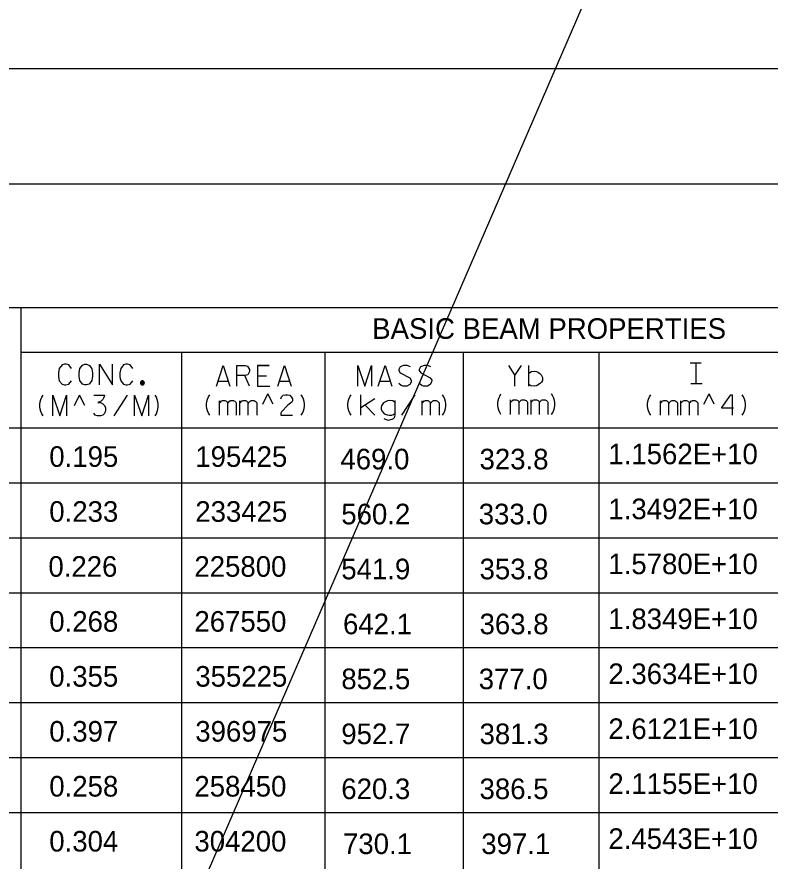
# Model space of a CAD drawing. Extents: x 635698 to 639877, y 296617 to 300175.
# Drawn here: x 636957.9 to 637067.5, y 299340.4 to 299463.3 of the extents above; entities that cross this region are included whole.
import ezdxf

# ---------------------------------------------------------------- set-up
doc = ezdxf.new("R2010")
doc.units = 0
doc.layers.add('1', color=7, linetype='Continuous')
doc.layers.add('2', color=7, linetype='Continuous')

msp = doc.modelspace()

# ---------------------------------------------------------------- linework, layer by layer
at = {"layer": '1'}
msp.add_line((637313.22, 300096.11), (636518.29, 298258.33), dxfattribs=at)
at = {"layer": '2'}
for p, q in [((636545.45, 299455.76), (637331.45, 299455.76)), ((637142.33, 299438.89), (636554.2, 299438.89)), ((637142.33, 299420.89), (636700.83, 299420.89)), ((636958.45, 299420.89), (636958.45, 299235.39)), ((637142.33, 299414.39), (636958.45, 299414.39)), ((636981.83, 299414.39), (636981.83, 299235.39)), ((637002.7, 299414.39), (637002.7, 299235.39)), ((637022.83, 299414.39), (637022.83, 299235.39)), ((637042.58, 299414.39), (637042.58, 299235.39)), ((637055.83, 299412.89), (637057.45, 299412.89)), ((637055.95, 299409.89), (637057.58, 299409.89)), ((636963.09, 299405.2), (636963.09, 299408.2)), ((636963.09, 299408.2), (636964.13, 299405.2)), ((636964.13, 299405.2), (636965.09, 299408.2)), ((636965.09, 299408.2), (636965.09, 299405.2)), ((636966.24, 299406.7), (636966.99, 299408.2)), ((636967.74, 299406.7), (636966.99, 299408.2)), ((636974.99, 299405.2), (636974.99, 299408.2)), ((636974.99, 299408.2), (636976.03, 299405.2)), ((636976.03, 299405.2), (636977, 299408.2)), ((636977, 299408.2), (636977, 299405.2)), ((636993.66, 299406.87), (636994.41, 299408.37)), ((636995.16, 299406.87), (636994.41, 299408.37)), ((637057.86, 299406.87), (637058.61, 299408.37)), ((637059.36, 299406.87), (637058.61, 299408.37)), ((637110.33, 299403.39), (636700.83, 299403.39)), ((637142.33, 299403.39), (636958.45, 299403.39)), ((637142.33, 299395.39), (636700.83, 299395.39)), ((637142.33, 299387.39), (636700.83, 299387.39)), ((637142.33, 299379.39), (636700.83, 299379.39)), ((637142.33, 299371.39), (636700.83, 299371.39)), ((637142.33, 299363.39), (636700.83, 299363.39)), ((637142.33, 299355.39), (636700.83, 299355.39)), ((637142.33, 299347.39), (636700.83, 299347.39))]:
    msp.add_line(p, q, dxfattribs=at)
for points in [[(636965.81, 299412.1), (636965.43, 299412.6), (636965.05, 299412.7), (636964.79, 299412.7), (636964.44, 299412.6), (636964.04, 299412.1), (636963.94, 299411.44), (636963.94, 299411.09), (636963.94, 299410.85), (636963.97, 299410.64), (636964.04, 299410.26), (636964.44, 299409.79), (636964.79, 299409.7), (636965.01, 299409.7), (636965.41, 299409.79), (636965.81, 299410.26)], [(636967.77, 299412.7), (636968.01, 299412.7), (636968.41, 299412.53), (636968.78, 299412.03), (636968.88, 299411.44), (636968.88, 299410.9), (636968.78, 299410.31), (636968.38, 299409.81), (636968.01, 299409.7), (636967.77, 299409.7), (636967.42, 299409.81), (636967.01, 299410.31), (636966.92, 299410.9), (636966.92, 299411.44), (636967.01, 299412.06), (636967.42, 299412.55), (636967.77, 299412.7)], [(636969.9, 299409.7), (636969.9, 299412.7), (636971.76, 299409.7), (636971.76, 299412.7)], [(636974.74, 299412.1), (636974.36, 299412.6), (636973.98, 299412.7), (636973.72, 299412.7), (636973.37, 299412.6), (636972.97, 299412.1), (636972.87, 299411.44), (636972.87, 299411.09), (636972.87, 299410.85), (636972.9, 299410.64), (636972.97, 299410.26), (636973.37, 299409.79), (636973.72, 299409.7), (636973.93, 299409.7), (636974.34, 299409.79), (636974.74, 299410.26)], [(636986.9, 299409.52), (636987.89, 299412.52), (636988.86, 299409.52)], [(636989.88, 299409.52), (636989.88, 299412.52), (636991.08, 299412.52), (636991.44, 299412.4), (636991.74, 299411.93), (636991.74, 299411.64), (636991.46, 299411.17), (636991.08, 299411.05), (636989.88, 299411.05)], [(636994.58, 299412.52), (636992.86, 299412.52), (636992.86, 299409.52), (636994.7, 299409.52)], [(636992.86, 299412.52), (636994.58, 299412.52)], [(636995.83, 299409.52), (636996.82, 299412.52), (636997.79, 299409.52)], [(637007.48, 299409.52), (637007.48, 299412.52), (637008.52, 299409.52), (637009.49, 299412.52), (637009.49, 299409.52)], [(637010.46, 299409.52), (637011.45, 299412.52), (637012.42, 299409.52)], [(637015.16, 299412.3), (637014.68, 299412.52), (637014.14, 299412.52), (637013.64, 299412.3), (637013.43, 299411.93), (637013.43, 299411.78), (637013.67, 299411.43), (637015.04, 299410.72), (637015.27, 299410.39), (637015.25, 299410.11), (637015.04, 299409.73), (637014.64, 299409.52), (637014.07, 299409.52), (637013.81, 299409.61), (637013.43, 299409.87)], [(637018.13, 299412.3), (637017.66, 299412.52), (637017.12, 299412.52), (637016.62, 299412.3), (637016.41, 299411.93), (637016.41, 299411.78), (637016.64, 299411.43), (637018.01, 299410.72), (637018.25, 299410.39), (637018.23, 299410.11), (637018.01, 299409.73), (637017.61, 299409.52), (637017.05, 299409.52), (637016.79, 299409.61), (637016.41, 299409.87)], [(637029.41, 299412.52), (637030.35, 299411.07), (637031.3, 299412.52)], [(637032.38, 299409.52), (637032.38, 299412.52)], [(637056.36, 299412.89), (637057.07, 299412.89)], [(637056.72, 299409.89), (637056.72, 299412.89)], [(636991.74, 299409.52), (636991.06, 299411.05)], [(636992.86, 299411.03), (636994.2, 299411.03)], [(636992.86, 299411.03), (636994.2, 299411.03)], [(637030.35, 299409.52), (637030.35, 299411.07)], [(637032.38, 299411.41), (637032.76, 299411.62), (637033.14, 299411.67), (637033.47, 299411.62), (637033.78, 299411.48), (637033.97, 299411.36), (637034.16, 299411.15), (637034.25, 299410.96), (637034.34, 299410.79), (637034.34, 299410.34), (637034.2, 299410.08), (637034.08, 299409.94), (637033.73, 299409.68), (637033.49, 299409.56), (637033.14, 299409.52), (637032.67, 299409.56), (637032.38, 299409.75)], [(636976.42, 299409.98), (636976.42, 299410.01), (636976.41, 299410.04), (636976.4, 299410.07), (636976.39, 299410.1), (636976.38, 299410.12), (636976.36, 299410.15), (636976.35, 299410.17), (636976.32, 299410.19), (636976.3, 299410.21), (636976.28, 299410.23), (636976.25, 299410.24), (636976.22, 299410.25), (636976.19, 299410.26), (636976.16, 299410.26), (636976.13, 299410.27), (636976.1, 299410.26), (636976.07, 299410.26), (636976.05, 299410.25), (636976.02, 299410.24), (636975.99, 299410.23), (636975.97, 299410.21), (636975.94, 299410.19), (636975.92, 299410.17), (636975.9, 299410.15), (636975.89, 299410.12), (636975.87, 299410.1), (636975.86, 299410.07), (636975.85, 299410.04), (636975.85, 299410.01), (636975.85, 299409.98), (636975.85, 299409.95), (636975.85, 299409.92), (636975.86, 299409.89), (636975.87, 299409.86), (636975.89, 299409.84), (636975.9, 299409.81), (636975.92, 299409.79), (636975.94, 299409.77), (636975.97, 299409.75), (636975.99, 299409.73), (636976.02, 299409.72), (636976.05, 299409.71), (636976.07, 299409.7), (636976.1, 299409.7), (636976.13, 299409.7), (636976.16, 299409.7), (636976.19, 299409.7), (636976.22, 299409.71), (636976.25, 299409.72), (636976.28, 299409.73), (636976.3, 299409.75), (636976.32, 299409.77), (636976.35, 299409.79), (636976.36, 299409.81), (636976.38, 299409.84), (636976.39, 299409.86), (636976.4, 299409.89), (636976.41, 299409.92), (636976.42, 299409.95), (636976.42, 299409.98)], [(636976.36, 299409.98), (636976.36, 299410), (636976.35, 299410.03), (636976.35, 299410.05), (636976.34, 299410.07), (636976.33, 299410.09), (636976.32, 299410.11), (636976.3, 299410.13), (636976.28, 299410.15), (636976.27, 299410.16), (636976.25, 299410.18), (636976.23, 299410.19), (636976.2, 299410.19), (636976.18, 299410.2), (636976.16, 299410.2), (636976.13, 299410.21), (636976.11, 299410.2), (636976.09, 299410.2), (636976.06, 299410.19), (636976.04, 299410.19), (636976.02, 299410.18), (636976, 299410.16), (636975.98, 299410.15), (636975.97, 299410.13), (636975.95, 299410.11), (636975.94, 299410.09), (636975.93, 299410.07), (636975.92, 299410.05), (636975.91, 299410.03), (636975.91, 299410), (636975.91, 299409.98), (636975.91, 299409.96), (636975.91, 299409.93), (636975.92, 299409.91), (636975.93, 299409.89), (636975.94, 299409.87), (636975.95, 299409.85), (636975.97, 299409.83), (636975.98, 299409.81), (636976, 299409.8), (636976.02, 299409.79), (636976.04, 299409.77), (636976.06, 299409.77), (636976.09, 299409.76), (636976.11, 299409.76), (636976.13, 299409.76), (636976.16, 299409.76), (636976.18, 299409.76), (636976.2, 299409.77), (636976.23, 299409.77), (636976.25, 299409.79), (636976.27, 299409.8), (636976.28, 299409.81), (636976.3, 299409.83), (636976.32, 299409.85), (636976.33, 299409.87), (636976.34, 299409.89), (636976.35, 299409.91), (636976.35, 299409.93), (636976.36, 299409.96), (636976.36, 299409.98)], [(636976.3, 299409.98), (636976.3, 299410), (636976.29, 299410.01), (636976.29, 299410.03), (636976.28, 299410.05), (636976.28, 299410.06), (636976.27, 299410.08), (636976.26, 299410.09), (636976.24, 299410.1), (636976.23, 299410.11), (636976.22, 299410.12), (636976.2, 299410.13), (636976.18, 299410.14), (636976.17, 299410.14), (636976.15, 299410.14), (636976.13, 299410.15), (636976.12, 299410.14), (636976.1, 299410.14), (636976.08, 299410.14), (636976.07, 299410.13), (636976.05, 299410.12), (636976.04, 299410.11), (636976.02, 299410.1), (636976.01, 299410.09), (636976, 299410.08), (636975.99, 299410.06), (636975.98, 299410.05), (636975.98, 299410.03), (636975.97, 299410.01), (636975.97, 299410), (636975.97, 299409.98), (636975.97, 299409.96), (636975.97, 299409.95), (636975.98, 299409.93), (636975.98, 299409.91), (636975.99, 299409.9), (636976, 299409.88), (636976.01, 299409.87), (636976.02, 299409.86), (636976.04, 299409.85), (636976.05, 299409.84), (636976.07, 299409.83), (636976.08, 299409.82), (636976.1, 299409.82), (636976.12, 299409.82), (636976.13, 299409.82), (636976.15, 299409.82), (636976.17, 299409.82), (636976.18, 299409.82), (636976.2, 299409.83), (636976.22, 299409.84), (636976.23, 299409.85), (636976.24, 299409.86), (636976.26, 299409.87), (636976.27, 299409.88), (636976.28, 299409.9), (636976.28, 299409.91), (636976.29, 299409.93), (636976.29, 299409.95), (636976.3, 299409.96), (636976.3, 299409.98)], [(636976.24, 299409.98), (636976.24, 299409.99), (636976.24, 299410), (636976.23, 299410.01), (636976.23, 299410.02), (636976.22, 299410.03), (636976.22, 299410.04), (636976.21, 299410.05), (636976.2, 299410.06), (636976.2, 299410.07), (636976.19, 299410.07), (636976.18, 299410.08), (636976.17, 299410.08), (636976.16, 299410.08), (636976.14, 299410.08), (636976.13, 299410.09), (636976.12, 299410.08), (636976.11, 299410.08), (636976.1, 299410.08), (636976.09, 299410.08), (636976.08, 299410.07), (636976.07, 299410.07), (636976.06, 299410.06), (636976.06, 299410.05), (636976.05, 299410.04), (636976.04, 299410.03), (636976.04, 299410.02), (636976.03, 299410.01), (636976.03, 299410), (636976.03, 299409.99), (636976.03, 299409.98), (636976.03, 299409.97), (636976.03, 299409.96), (636976.03, 299409.95), (636976.04, 299409.94), (636976.04, 299409.93), (636976.05, 299409.92), (636976.06, 299409.91), (636976.06, 299409.9), (636976.07, 299409.9), (636976.08, 299409.89), (636976.09, 299409.88), (636976.1, 299409.88), (636976.11, 299409.88), (636976.12, 299409.88), (636976.13, 299409.88), (636976.14, 299409.88), (636976.16, 299409.88), (636976.17, 299409.88), (636976.18, 299409.88), (636976.19, 299409.89), (636976.2, 299409.9), (636976.2, 299409.9), (636976.21, 299409.91), (636976.22, 299409.92), (636976.22, 299409.93), (636976.23, 299409.94), (636976.23, 299409.95), (636976.24, 299409.96), (636976.24, 299409.97), (636976.24, 299409.98)], [(636976.18, 299409.98), (636976.18, 299409.99), (636976.18, 299409.99), (636976.18, 299409.99), (636976.17, 299410), (636976.17, 299410), (636976.17, 299410.01), (636976.17, 299410.01), (636976.16, 299410.01), (636976.16, 299410.02), (636976.16, 299410.02), (636976.15, 299410.02), (636976.15, 299410.02), (636976.14, 299410.02), (636976.14, 299410.02), (636976.13, 299410.03), (636976.13, 299410.02), (636976.12, 299410.02), (636976.12, 299410.02), (636976.12, 299410.02), (636976.11, 299410.02), (636976.11, 299410.02), (636976.1, 299410.01), (636976.1, 299410.01), (636976.1, 299410.01), (636976.09, 299410), (636976.09, 299410), (636976.09, 299409.99), (636976.09, 299409.99), (636976.09, 299409.99), (636976.09, 299409.98), (636976.09, 299409.98), (636976.09, 299409.97), (636976.09, 299409.97), (636976.09, 299409.96), (636976.09, 299409.96), (636976.1, 299409.95), (636976.1, 299409.95), (636976.1, 299409.95), (636976.11, 299409.94), (636976.11, 299409.94), (636976.12, 299409.94), (636976.12, 299409.94), (636976.12, 299409.94), (636976.13, 299409.94), (636976.13, 299409.94), (636976.14, 299409.94), (636976.14, 299409.94), (636976.15, 299409.94), (636976.15, 299409.94), (636976.16, 299409.94), (636976.16, 299409.94), (636976.16, 299409.95), (636976.17, 299409.95), (636976.17, 299409.95), (636976.17, 299409.96), (636976.17, 299409.96), (636976.18, 299409.97), (636976.18, 299409.97), (636976.18, 299409.98), (636976.18, 299409.98)], [(636987.14, 299410.22), (636988.63, 299410.22)], [(636996.07, 299410.22), (636997.56, 299410.22)], [(637010.69, 299410.22), (637012.18, 299410.22)], [(637056.36, 299409.89), (637057.07, 299409.89)], [(636961.68, 299405.2), (636961.49, 299405.5), (636961.35, 299405.83), (636961.26, 299406.16), (636961.21, 299406.52), (636961.21, 299406.87), (636961.26, 299407.23), (636961.35, 299407.56), (636961.49, 299407.89), (636961.68, 299408.2)], [(636969.04, 299408.2), (636970.62, 299408.2), (636970.53, 299407.84), (636970.36, 299407.58), (636970.13, 299407.34), (636969.65, 299407.11), (636970.01, 299407.11), (636970.39, 299406.94), (636970.62, 299406.71), (636970.74, 299406.33), (636970.74, 299405.93), (636970.62, 299405.53), (636970.36, 299405.29), (636970.01, 299405.2), (636969.61, 299405.2), (636969.25, 299405.29), (636969.04, 299405.55)], [(636972.02, 299405.2), (636973.98, 299408.2)], [(636977.97, 299405.2), (636978.16, 299405.5), (636978.3, 299405.83), (636978.39, 299406.16), (636978.44, 299406.52), (636978.44, 299406.87), (636978.39, 299407.23), (636978.3, 299407.56), (636978.16, 299407.89), (636977.97, 299408.2)], [(636985.93, 299405.26), (636985.74, 299405.57), (636985.6, 299405.9), (636985.51, 299406.23), (636985.46, 299406.58), (636985.46, 299406.94), (636985.51, 299407.29), (636985.6, 299407.62), (636985.74, 299407.95), (636985.93, 299408.26)], [(636987.34, 299407.01), (636987.38, 299407.06), (636987.43, 299407.15), (636987.64, 299407.36), (636987.71, 299407.39), (636987.81, 299407.41), (636988.14, 299407.41), (636988.28, 299407.36), (636988.38, 299407.29), (636988.47, 299407.2), (636988.54, 299407.03), (636988.56, 299406.99), (636988.61, 299407.06), (636988.66, 299407.15), (636988.87, 299407.36), (636988.94, 299407.39), (636989.01, 299407.41), (636989.37, 299407.41), (636989.46, 299407.36), (636989.58, 299407.32), (636989.7, 299407.22), (636989.75, 299407.15), (636989.79, 299407.06), (636989.79, 299405.26)], [(636987.34, 299405.26), (636987.34, 299407.39)], [(636990.31, 299407.01), (636990.36, 299407.06), (636990.41, 299407.15), (636990.62, 299407.36), (636990.69, 299407.39), (636990.78, 299407.41), (636991.12, 299407.41), (636991.26, 299407.36), (636991.35, 299407.29), (636991.45, 299407.2), (636991.52, 299407.03), (636991.54, 299406.99), (636991.59, 299407.06), (636991.64, 299407.15), (636991.85, 299407.36), (636991.92, 299407.39), (636991.99, 299407.41), (636992.34, 299407.41), (636992.44, 299407.36), (636992.56, 299407.32), (636992.67, 299407.22), (636992.72, 299407.15), (636992.77, 299407.06), (636992.77, 299405.26)], [(636990.31, 299405.26), (636990.31, 299407.39)], [(636996.27, 299407.65), (636996.36, 299407.93), (636996.62, 299408.17), (636996.97, 299408.26), (636997.23, 299408.26), (636997.59, 299408.17), (636997.85, 299407.91), (636997.97, 299407.65), (636997.97, 299407.39), (636997.87, 299407.18), (636997.28, 299406.73), (636996.36, 299405.78), (636996.27, 299405.55), (636996.27, 299405.26), (636997.97, 299405.26)], [(636999.24, 299405.26), (636999.43, 299405.57), (636999.57, 299405.9), (636999.67, 299406.23), (636999.71, 299406.58), (636999.71, 299406.94), (636999.67, 299407.29), (636999.57, 299407.62), (636999.43, 299407.95), (636999.24, 299408.26)], [(637006.51, 299405.26), (637006.32, 299405.57), (637006.18, 299405.9), (637006.08, 299406.23), (637006.04, 299406.58), (637006.04, 299406.94), (637006.08, 299407.29), (637006.18, 299407.62), (637006.32, 299407.95), (637006.51, 299408.26)], [(637007.91, 299405.26), (637007.91, 299408.26)], [(637009.94, 299407.65), (637007.91, 299406.35)], [(637012.87, 299407.15), (637012.57, 299407.36), (637012.12, 299407.41), (637011.79, 299407.39), (637011.22, 299407.08), (637010.94, 299406.66), (637010.89, 299406.42), (637010.89, 299406.18), (637010.98, 299405.9), (637011.24, 299405.62), (637011.46, 299405.45), (637011.76, 299405.31), (637012.05, 299405.26), (637012.42, 299405.29), (637012.66, 299405.36), (637012.87, 299405.52)], [(637012.87, 299407.41), (637012.87, 299405.26), (637012.83, 299405.07), (637012.75, 299404.91), (637012.61, 299404.74), (637012.42, 299404.65), (637012.21, 299404.58), (637011.95, 299404.53), (637011.64, 299404.58), (637011.34, 299404.74)], [(637013.87, 299405.26), (637015.83, 299408.26)], [(637016.84, 299407.01), (637016.89, 299407.06), (637016.94, 299407.15), (637017.15, 299407.36), (637017.22, 299407.39), (637017.31, 299407.41), (637017.65, 299407.41), (637017.79, 299407.36), (637017.88, 299407.29), (637017.98, 299407.2), (637018.05, 299407.03), (637018.07, 299406.99), (637018.12, 299407.06), (637018.16, 299407.15), (637018.38, 299407.36), (637018.45, 299407.39), (637018.52, 299407.41), (637018.87, 299407.41), (637018.97, 299407.36), (637019.09, 299407.32), (637019.2, 299407.22), (637019.25, 299407.15), (637019.3, 299407.06), (637019.3, 299405.26)], [(637016.84, 299405.26), (637016.84, 299407.39)], [(637019.82, 299405.26), (637020.01, 299405.57), (637020.15, 299405.9), (637020.24, 299406.23), (637020.29, 299406.58), (637020.29, 299406.94), (637020.24, 299407.29), (637020.15, 299407.62), (637020.01, 299407.95), (637019.82, 299408.26)], [(637028.32, 299405.38), (637028.13, 299405.69), (637027.99, 299406.02), (637027.9, 299406.35), (637027.85, 299406.7), (637027.85, 299407.06), (637027.9, 299407.41), (637027.99, 299407.74), (637028.13, 299408.07), (637028.32, 299408.38)], [(637029.72, 299407.13), (637029.77, 299407.17), (637029.82, 299407.27), (637030.03, 299407.48), (637030.1, 299407.51), (637030.2, 299407.53), (637030.53, 299407.53), (637030.67, 299407.48), (637030.76, 299407.41), (637030.86, 299407.32), (637030.93, 299407.15), (637030.95, 299407.1), (637031, 299407.17), (637031.05, 299407.27), (637031.26, 299407.48), (637031.33, 299407.51), (637031.4, 299407.53), (637031.76, 299407.53), (637031.85, 299407.48), (637031.97, 299407.43), (637032.09, 299407.34), (637032.13, 299407.27), (637032.18, 299407.17), (637032.18, 299405.38)], [(637029.72, 299405.38), (637029.72, 299407.51)], [(637032.7, 299407.13), (637032.75, 299407.17), (637032.79, 299407.27), (637033.01, 299407.48), (637033.08, 299407.51), (637033.17, 299407.53), (637033.5, 299407.53), (637033.64, 299407.48), (637033.74, 299407.41), (637033.83, 299407.32), (637033.9, 299407.15), (637033.93, 299407.1), (637033.98, 299407.17), (637034.02, 299407.27), (637034.24, 299407.48), (637034.31, 299407.51), (637034.38, 299407.53), (637034.73, 299407.53), (637034.83, 299407.48), (637034.94, 299407.43), (637035.06, 299407.34), (637035.11, 299407.27), (637035.16, 299407.17), (637035.16, 299405.38)], [(637032.7, 299405.38), (637032.7, 299407.51)], [(637035.68, 299405.38), (637035.87, 299405.69), (637036.01, 299406.02), (637036.1, 299406.35), (637036.15, 299406.7), (637036.15, 299407.06), (637036.1, 299407.41), (637036.01, 299407.74), (637035.87, 299408.07), (637035.68, 299408.38)], [(637050.13, 299405.26), (637049.94, 299405.57), (637049.8, 299405.9), (637049.71, 299406.23), (637049.66, 299406.58), (637049.66, 299406.94), (637049.71, 299407.29), (637049.8, 299407.62), (637049.94, 299407.95), (637050.13, 299408.26)], [(637051.53, 299407.01), (637051.58, 299407.06), (637051.63, 299407.15), (637051.84, 299407.36), (637051.91, 299407.39), (637052.01, 299407.41), (637052.34, 299407.41), (637052.48, 299407.36), (637052.57, 299407.29), (637052.67, 299407.2), (637052.74, 299407.03), (637052.76, 299406.99), (637052.81, 299407.06), (637052.86, 299407.15), (637053.07, 299407.36), (637053.14, 299407.39), (637053.21, 299407.41), (637053.57, 299407.41), (637053.66, 299407.36), (637053.78, 299407.32), (637053.9, 299407.22), (637053.94, 299407.15), (637053.99, 299407.06), (637053.99, 299405.26)], [(637051.53, 299405.26), (637051.53, 299407.39)], [(637054.51, 299407.01), (637054.56, 299407.06), (637054.61, 299407.15), (637054.82, 299407.36), (637054.89, 299407.39), (637054.98, 299407.41), (637055.31, 299407.41), (637055.46, 299407.36), (637055.55, 299407.29), (637055.64, 299407.2), (637055.72, 299407.03), (637055.74, 299406.99), (637055.79, 299407.06), (637055.83, 299407.15), (637056.05, 299407.36), (637056.12, 299407.39), (637056.19, 299407.41), (637056.54, 299407.41), (637056.64, 299407.36), (637056.75, 299407.32), (637056.87, 299407.22), (637056.92, 299407.15), (637056.97, 299407.06), (637056.97, 299405.26)], [(637054.51, 299405.26), (637054.51, 299407.39)], [(637062.16, 299406.3), (637060.46, 299406.3), (637060.46, 299406.42), (637061.79, 299408.26), (637061.95, 299408.26), (637061.95, 299405.26)], [(637063.44, 299405.26), (637063.63, 299405.57), (637063.77, 299405.9), (637063.87, 299406.23), (637063.91, 299406.58), (637063.91, 299406.94), (637063.87, 299407.29), (637063.77, 299407.62), (637063.63, 299407.95), (637063.44, 299408.26)], [(636988.56, 299405.26), (636988.56, 299407.01)], [(636991.54, 299405.26), (636991.54, 299407.01)], [(637008.55, 299406.75), (637009.94, 299405.26)], [(637018.07, 299405.26), (637018.07, 299407.01)], [(637030.95, 299405.38), (637030.95, 299407.13)], [(637033.93, 299405.38), (637033.93, 299407.13)], [(637052.76, 299405.26), (637052.76, 299407.01)], [(637055.74, 299405.26), (637055.74, 299407.01)]]:
    msp.add_lwpolyline(points, dxfattribs=at)

# ---------------------------------------------------------------- texts
for s, p in [('BASIC BEAM PROPERTIES', (637009.58, 299416.39)), ('1.1562E+10', (637043.95, 299398.14)), ('0.195', (636962.58, 299397.76)), ('195425', (636983.83, 299397.76)), ('469.0', (637004.95, 299397.39)), ('323.8', (637025.2, 299397.39)), ('0.233', (636962.58, 299389.76)), ('233425', (636983.83, 299389.76)), ('1.3492E+10', (637043.95, 299390.14)), ('560.2', (637005.08, 299389.39)), ('333.0', (637025.08, 299389.39)), ('0.226', (636962.45, 299381.76)), ('225800', (636983.7, 299381.76)), ('541.9', (637005.08, 299381.39)), ('353.8', (637025.2, 299381.39)), ('1.5780E+10', (637043.95, 299382.14)), ('0.268', (636962.58, 299373.76)), ('267550', (636983.7, 299373.76)), ('1.8349E+10', (637043.95, 299374.14)), ('642.1', (637005.33, 299373.39)), ('363.8', (637025.2, 299373.39)), ('0.355', (636962.58, 299365.76)), ('355225', (636983.83, 299365.76)), ('852.5', (637005.08, 299365.39)), ('377.0', (637025.08, 299365.39)), ('2.3634E+10', (637043.95, 299366.14)), ('0.397', (636962.58, 299357.76)), ('396975', (636983.83, 299357.76)), ('2.6121E+10', (637043.95, 299358.14)), ('952.7', (637005.08, 299357.39)), ('381.3', (637025.2, 299357.39)), ('0.258', (636962.58, 299349.76)), ('258450', (636983.7, 299349.76)), ('620.3', (637005.08, 299349.39)), ('386.5', (637025.2, 299349.39)), ('2.1155E+10', (637043.95, 299350.14)), ('0.304', (636962.58, 299341.76)), ('304200', (636983.7, 299341.76)), ('2.4543E+10', (637043.95, 299342.14)), ('730.1', (637005.33, 299341.39)), ('397.1', (637025.45, 299341.39))]:
    msp.add_text(s, height=3, dxfattribs=at).set_placement(p)

doc.saveas('drawing.dxf')
